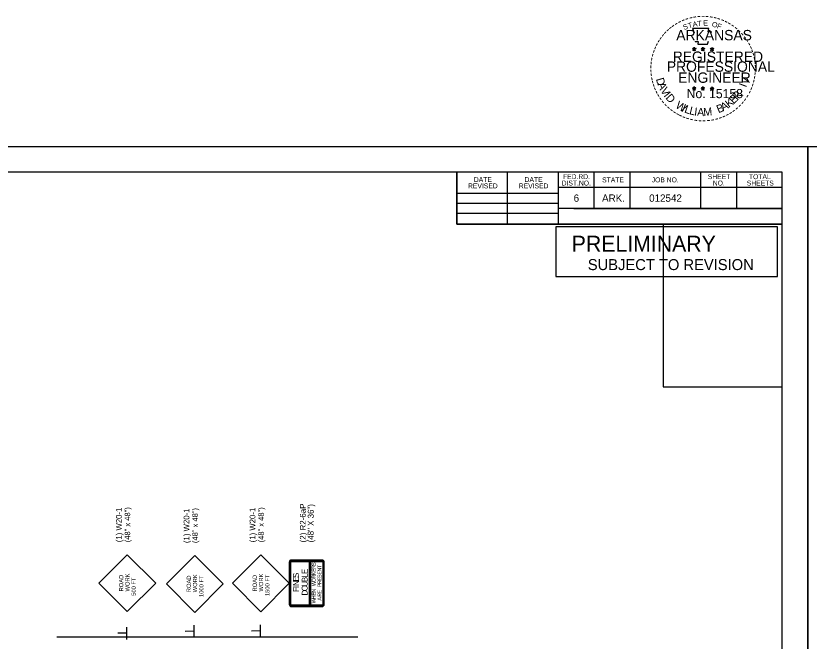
# Model space of a CAD drawing. Extents: x 32485 to 39285, y 55121 to 58033.
# Drawn here: x 35108 to 35886, y 57379 to 57992 of the extents above; entities that cross this region are included whole.
import ezdxf

# ---------------------------------------------------------------- set-up
doc = ezdxf.new("R2010")
doc.units = 0
for name, color, linetype in [('Default', 7, 'Continuous'), ('R_Border', 7, 'Continuous'), ('R_Border Notes', 7, 'Continuous'), ('R_Border PE', 7, 'Continuous'), ('R_Dimension', 7, 'Continuous'), ('R_Draft', 7, 'Continuous'), ('R_Exist Surface', 7, 'Continuous'), ('SHET_Annotations', 7, 'Continuous'), ('SHET_Border-Lines', 7, 'Continuous'), ('SHET_Border-Text', 7, 'Continuous'), ('SHET_Stamp-Seal', 7, 'Continuous')]:
    doc.layers.add(name, color=color, linetype=linetype)

msp = doc.modelspace()

# ---------------------------------------------------------------- linework, layer by layer
at = {"layer": 'Default'}
for p, q in [((35376.16, 57456.07), (35376.16, 57414.67)), ((35376.75, 57456.07), (35376.75, 57414.67)), ((35377.59, 57414.67), (35377.59, 57456.07)), ((35408.28, 57458.21), (35378.3, 57458.21)), ((35408.28, 57457.62), (35378.3, 57457.62)), ((35378.3, 57456.78), (35408.28, 57456.78)), ((35395.97, 57413.96), (35395.97, 57456.78)), ((35395.97, 57456.78), (35396.8, 57456.78)), ((35396.8, 57456.78), (35396.8, 57413.96)), ((35408.99, 57456.07), (35408.99, 57414.67)), ((35409.83, 57414.67), (35409.83, 57456.07)), ((35410.42, 57414.67), (35410.42, 57456.07)), ((35408.28, 57413.96), (35378.3, 57413.96)), ((35378.3, 57413.12), (35408.28, 57413.12)), ((35378.3, 57412.53), (35408.28, 57412.53)), ((35396.8, 57413.96), (35395.97, 57413.96))]:
    msp.add_line(p, q, dxfattribs=at)
for points in [[(34185, 57863.91), (34185, 56763.91), (35885, 56763.91), (35885, 57863.91)], [(35885, 57863.91), (35885, 56763.91), (37585, 56763.91), (37585, 57863.91)], [(35637.83, 57736.64), (35855.24, 57736.64), (35855.24, 57785.18), (35637.83, 57785.18)]]:
    msp.add_lwpolyline(points, close=True, dxfattribs=at)
for centre, radius, start, end in [((35378.3, 57456.07), 2.14, 90, 180), ((35378.3, 57456.07), 1.55, 90, 180), ((35378.3, 57456.07), 0.714, 90, 180), ((35408.28, 57456.07), 2.14, 0.00001, 90.00001), ((35408.28, 57456.07), 1.55, 0, 90.00001), ((35408.28, 57456.07), 0.714, 0, 90.00001), ((35378.3, 57414.67), 2.14, 180, 270), ((35378.3, 57414.67), 1.55, 180, 270.00001), ((35378.3, 57414.67), 0.714, 180, 270.00001), ((35408.28, 57414.67), 2.14, 270, 0.00001), ((35408.28, 57414.67), 1.55, 270.00001, 0), ((35408.28, 57414.67), 0.714, 270.00001, 0)]:
    msp.add_arc(centre, radius, start, end, dxfattribs=at)
at = {"layer": 'R_Border'}
for p, q in [((35217.11, 57463.36), (35189.21, 57435.46)), ((35217.11, 57463.36), (35244.99, 57435.46)), ((35283.48, 57462.55), (35255.58, 57434.66)), ((35283.48, 57462.55), (35311.36, 57434.66)), ((35348.28, 57463.27), (35320.38, 57435.37)), ((35348.28, 57463.27), (35376.16, 57435.37)), ((35189.21, 57435.46), (35217.11, 57407.56)), ((35244.99, 57435.46), (35217.11, 57407.56)), ((35255.58, 57434.66), (35283.48, 57406.76)), ((35311.36, 57434.66), (35283.48, 57406.76)), ((35320.38, 57435.37), (35348.28, 57407.47)), ((35376.16, 57435.37), (35348.28, 57407.47)), ((35216.17, 57392.37), (35216.37, 57380.32)), ((35282.33, 57394.28), (35282.54, 57382.24)), ((35347.42, 57394.58), (35347.63, 57382.54)), ((35216.09, 57386.38), (35207.87, 57386.24)), ((35282.26, 57388.29), (35274.03, 57388.15)), ((35347.35, 57388.59), (35339.12, 57388.45))]:
    msp.add_line(p, q, dxfattribs=at)
at = {"layer": 'R_Border Notes'}
for p, q in [((35540.54, 57787.97), (35540.54, 57838.91)), ((35590.37, 57787.97), (35590.37, 57838.91)), ((35640.19, 57838.91), (35640.19, 57787.97)), ((35675.08, 57838.91), (35675.08, 57803.13)), ((35710.47, 57838.91), (35710.47, 57803.13)), ((35779.73, 57838.91), (35779.73, 57803.13)), ((35815.12, 57838.91), (35815.12, 57803.13)), ((35860, 57823.75), (35640.19, 57823.75)), ((35860, 57823.85), (35860, 57823.85)), ((35540.54, 57818.18), (35640.19, 57818.18)), ((35540.54, 57808.59), (35640.19, 57808.59)), ((35540.54, 57798.59), (35640.19, 57798.59)), ((35860, 57803.13), (35640.19, 57803.13)), ((35655.29, 57803.13), (35860, 57803.13)), ((35860, 57787.97), (35540.54, 57787.97))]:
    msp.add_line(p, q, dxfattribs=at)
for points in [[(34185, 56763.91), (35885, 56763.91), (35885, 57863.91), (34185, 57863.91)], [(35885, 56763.91), (37585, 56763.91), (37585, 57863.91), (35885, 57863.91)], [(34210, 56788.91), (35860, 56788.91), (35860, 57838.91), (34210, 57838.91)], [(35540.54, 57787.97), (35860, 57787.97), (35860, 57838.91), (35540.54, 57838.91)]]:
    msp.add_lwpolyline(points, close=True, dxfattribs=at)
at = {"layer": 'R_Border PE'}
msp.add_lwpolyline([(35773.62, 57961.48), (35774.71, 57958.11), (35771.84, 57960.19), (35775.39, 57960.19), (35772.52, 57958.11), (35773.62, 57961.48)], dxfattribs=at)
at = {"layer": 'R_Dimension'}
for p, q in [((35771.84, 57960.19), (35773.62, 57959.62)), ((35771.84, 57960.19), (35773.13, 57959.96)), ((35771.84, 57960.19), (35773.05, 57959.56)), ((35772.52, 57958.11), (35773.62, 57959.62)), ((35772.52, 57958.11), (35773.16, 57959.35)), ((35772.52, 57958.11), (35773.61, 57959.21)), ((35773.62, 57961.48), (35773.41, 57960.2)), ((35774.71, 57958.11), (35773.61, 57959.2)), ((35773.62, 57959.62), (35773.62, 57961.48)), ((35773.62, 57961.48), (35773.87, 57960.21)), ((35775.39, 57960.19), (35773.62, 57959.62)), ((35774.71, 57958.11), (35773.62, 57959.62)), ((35775.39, 57960.19), (35773.93, 57959.94)), ((35774.71, 57958.11), (35774.01, 57959.59)), ((35775.39, 57960.19), (35774.35, 57959.67)), ((35780.36, 57960.19), (35782.14, 57959.62)), ((35780.36, 57960.19), (35781.65, 57959.96)), ((35780.36, 57960.19), (35781.57, 57959.56)), ((35781.04, 57958.11), (35782.14, 57959.62)), ((35781.04, 57958.11), (35781.68, 57959.35)), ((35781.04, 57958.11), (35782.13, 57959.21)), ((35782.14, 57961.48), (35781.93, 57960.2)), ((35783.22, 57958.11), (35782.13, 57959.2)), ((35782.14, 57959.62), (35782.14, 57961.48)), ((35782.14, 57961.48), (35782.39, 57960.21)), ((35783.91, 57960.19), (35782.14, 57959.62)), ((35783.22, 57958.11), (35782.14, 57959.62)), ((35783.91, 57960.19), (35782.45, 57959.94)), ((35783.22, 57958.11), (35782.52, 57959.59)), ((35783.91, 57960.19), (35782.87, 57959.67)), ((35789.35, 57960.13), (35791.13, 57959.56)), ((35789.35, 57960.13), (35790.64, 57959.9)), ((35789.35, 57960.13), (35790.56, 57959.5)), ((35790.03, 57958.04), (35791.13, 57959.56)), ((35790.03, 57958.04), (35790.67, 57959.29)), ((35790.03, 57958.04), (35791.12, 57959.15)), ((35791.13, 57961.42), (35790.92, 57960.14)), ((35792.22, 57958.04), (35791.12, 57959.14)), ((35791.13, 57959.56), (35791.13, 57961.42)), ((35791.13, 57961.42), (35791.38, 57960.15)), ((35792.9, 57960.13), (35791.13, 57959.56)), ((35792.22, 57958.04), (35791.13, 57959.56)), ((35792.9, 57960.13), (35791.44, 57959.88)), ((35792.22, 57958.04), (35791.52, 57959.53)), ((35792.9, 57960.13), (35791.86, 57959.61)), ((35771.82, 57921.57), (35773.6, 57921)), ((35771.82, 57921.57), (35773.11, 57921.34)), ((35771.82, 57921.57), (35773.03, 57920.94)), ((35772.5, 57919.48), (35773.6, 57921)), ((35772.5, 57919.48), (35773.14, 57920.73)), ((35772.5, 57919.48), (35773.59, 57920.59)), ((35773.6, 57922.86), (35773.39, 57921.58)), ((35774.69, 57919.48), (35773.59, 57920.58)), ((35773.6, 57921), (35773.6, 57922.86)), ((35773.6, 57922.86), (35773.85, 57921.59)), ((35775.37, 57921.57), (35773.6, 57921)), ((35774.69, 57919.48), (35773.6, 57921)), ((35775.37, 57921.57), (35773.91, 57921.32)), ((35774.69, 57919.48), (35773.99, 57920.97)), ((35775.37, 57921.57), (35774.33, 57921.05)), ((35780.33, 57921.57), (35782.11, 57921)), ((35780.33, 57921.57), (35781.62, 57921.34)), ((35780.33, 57921.57), (35781.54, 57920.94)), ((35781.01, 57919.48), (35782.11, 57921)), ((35781.01, 57919.48), (35781.65, 57920.73)), ((35781.01, 57919.48), (35782.1, 57920.59)), ((35782.11, 57922.86), (35781.9, 57921.58)), ((35783.2, 57919.48), (35782.1, 57920.58)), ((35782.11, 57921), (35782.11, 57922.86)), ((35782.11, 57922.86), (35782.36, 57921.59)), ((35783.88, 57921.57), (35782.11, 57921)), ((35783.2, 57919.48), (35782.11, 57921)), ((35783.88, 57921.57), (35782.42, 57921.32)), ((35783.2, 57919.48), (35782.5, 57920.97)), ((35783.88, 57921.57), (35782.84, 57921.05)), ((35789.34, 57921.51), (35791.12, 57920.95)), ((35789.34, 57921.51), (35790.63, 57921.28)), ((35789.34, 57921.51), (35790.55, 57920.89)), ((35790.02, 57919.43), (35791.12, 57920.95)), ((35790.02, 57919.43), (35790.66, 57920.68)), ((35790.02, 57919.43), (35791.11, 57920.54)), ((35791.12, 57922.81), (35790.91, 57921.52)), ((35792.21, 57919.43), (35791.11, 57920.52)), ((35791.12, 57920.95), (35791.12, 57922.81)), ((35791.12, 57922.81), (35791.37, 57921.53)), ((35792.89, 57921.51), (35791.12, 57920.95)), ((35792.21, 57919.43), (35791.12, 57920.95)), ((35792.89, 57921.51), (35791.43, 57921.26)), ((35792.21, 57919.43), (35791.51, 57920.92)), ((35792.89, 57921.51), (35791.85, 57920.99))]:
    msp.add_line(p, q, dxfattribs=at)
for points in [[(35772.05, 57979.96), (35773.42, 57975.75)], [(35789.95, 57975.26), (35790.68, 57976.71), (35787.19, 57976.59), (35787.94, 57979.96), (35772.05, 57979.96)], [(35774.56, 57967.61), (35774.56, 57967.16), (35777.43, 57967.07), (35777.15, 57964.65), (35786.69, 57964.65), (35787.72, 57967.39)], [(35782.14, 57961.48), (35783.22, 57958.11), (35780.36, 57960.19), (35783.91, 57960.19), (35781.04, 57958.11), (35782.14, 57961.48)], [(35791.13, 57961.42), (35792.22, 57958.04), (35789.35, 57960.13), (35792.9, 57960.13), (35790.03, 57958.04), (35791.13, 57961.42)], [(35773.6, 57922.86), (35774.69, 57919.48), (35771.82, 57921.57), (35775.37, 57921.57), (35772.5, 57919.48), (35773.6, 57922.86)], [(35782.11, 57922.86), (35783.2, 57919.48), (35780.33, 57921.57), (35783.88, 57921.57), (35781.01, 57919.48), (35782.11, 57922.86)], [(35791.12, 57922.81), (35792.21, 57919.43), (35789.34, 57921.51), (35792.89, 57921.51), (35790.02, 57919.43), (35791.12, 57922.81)]]:
    msp.add_lwpolyline(points, dxfattribs=at)
for centre, radius in [((35773.61, 57959.62), 0.878), ((35773.61, 57959.62), 0.737), ((35773.61, 57959.62), 0.59), ((35773.61, 57959.62), 0.505), ((35773.61, 57959.62), 0.381), ((35773.61, 57959.62), 0.253), ((35773.61, 57959.62), 0.151), ((35782.13, 57959.62), 0.878), ((35782.13, 57959.62), 0.737), ((35782.13, 57959.62), 0.59), ((35782.13, 57959.62), 0.505), ((35782.13, 57959.62), 0.381), ((35782.13, 57959.62), 0.253), ((35782.13, 57959.62), 0.151), ((35791.13, 57959.56), 0.878), ((35791.13, 57959.56), 0.737), ((35791.13, 57959.56), 0.59), ((35791.13, 57959.56), 0.505), ((35791.13, 57959.56), 0.381), ((35791.13, 57959.56), 0.253), ((35791.13, 57959.56), 0.151), ((35773.59, 57920.99), 0.878), ((35773.59, 57920.99), 0.737), ((35773.59, 57920.99), 0.59), ((35773.59, 57920.99), 0.505), ((35773.59, 57920.99), 0.381), ((35773.59, 57920.99), 0.253), ((35773.59, 57920.99), 0.151), ((35782.11, 57920.99), 0.878), ((35782.11, 57920.99), 0.737), ((35782.11, 57920.99), 0.59), ((35782.11, 57920.99), 0.505), ((35782.11, 57920.99), 0.381), ((35782.11, 57920.99), 0.253), ((35782.11, 57920.99), 0.151), ((35791.12, 57920.94), 0.878), ((35791.12, 57920.94), 0.737), ((35791.12, 57920.94), 0.59), ((35791.12, 57920.94), 0.505), ((35791.12, 57920.94), 0.381), ((35791.12, 57920.94), 0.253), ((35791.12, 57920.94), 0.151)]:
    msp.add_circle(centre, radius, dxfattribs=at)
at = {"layer": 'R_Exist Surface'}
msp.add_line((35148.06, 57382.7), (35443.42, 57382.7), dxfattribs=at)
at = {"layer": 'SHET_Border-Text'}
msp.add_lwpolyline([(35742.99, 57628.25), (35860, 57628.25), (35860, 57787.97), (35742.99, 57787.97)], close=True, dxfattribs=at)
at = {"layer": 'SHET_Stamp-Seal'}
msp.add_lwpolyline([(35750.01, 57787.93), (35750.19, 57787.93), (35750.19, 57787.97), (35750.01, 57787.97)], close=True, dxfattribs=at)

# ---------------------------------------------------------------- texts
at = {"layer": 'Default'}
for s, height, p in [('PRELIMINARY', 15.6, (35653.4, 57760.91)), ('SUBJECT TO REVISION', 10.8, (35669.17, 57742.77))]:
    msp.add_text(s, height=height, dxfattribs=at).set_placement(p)
for s, height, p in [('S', 3.81, (35402.03, 57452.48)), ('R', 3.81, (35402.03, 57449.51)), ('T', 3.81, (35407.74, 57450.07)), ('S', 5.71, (35385.5, 57440.68)), ('E', 5.71, (35394.06, 57444.45)), ('E', 3.81, (35402.03, 57446.51)), ('K', 3.81, (35402.03, 57443.19)), ('N', 3.81, (35407.74, 57446.91)), ('E', 3.81, (35407.74, 57443.9)), ('E', 5.71, (35385.5, 57437.08)), ('N', 5.71, (35385.5, 57432.63)), ('L', 5.71, (35394.06, 57440.74)), ('B', 5.71, (35394.06, 57436.57)), ('O', 3.81, (35402.03, 57436.42)), ('R', 3.81, (35402.03, 57439.96)), ('S', 3.81, (35407.74, 57440.66)), ('E', 3.81, (35407.74, 57437.92)), ('R', 3.81, (35407.74, 57434.68)), ('I', 5.71, (35385.5, 57430.57)), ('F', 5.71, (35385.5, 57426.86)), ('O', 5.71, (35394.06, 57427.6)), ('U', 5.71, (35394.06, 57432.12)), ('W', 3.81, (35402.03, 57432.53)), ('P', 3.81, (35407.74, 57431.53)), ('D', 5.71, (35394.06, 57423.38)), ('N', 3.81, (35402.03, 57426.14)), ('E', 3.81, (35402.03, 57423.13)), ('H', 3.81, (35402.03, 57419.63)), ('E', 3.81, (35407.74, 57425.36)), ('R', 3.81, (35407.74, 57422.12)), ('W', 3.81, (35402.03, 57415.67)), ('A', 3.81, (35407.74, 57418.31))]:
    msp.add_text(s, height=height, rotation=90, dxfattribs=at).set_placement(p)
at = {"layer": 'R_Border'}
for s, height, rotation, p in [('(1) W20-1', 5.71, 90, (35211.71, 57475.64)), ('(48" x 48")', 5.3523, 90, (35219.93, 57475.64)), ('(1) W20-1', 5.71, 90, (35278.08, 57474.83)), ('(48" x 48")', 5.3523, 90, (35286.3, 57474.83)), ('(1) W20-1', 5.71, 90, (35342.88, 57475.55)), ('(48" x 48")', 5.3523, 90, (35351.09, 57475.55)), ('ROAD', 4.11, 90.00045, (35213.13, 57427.4)), ('WORK', 4.11, 90.00004, (35219.3, 57427.32)), (' 500 FT', 4.11, 90.00057, (35225.46, 57421.51)), ('ROAD', 4.11, 90.00045, (35279.51, 57426.6)), ('WORK', 4.11, 90.00004, (35285.67, 57426.52)), ('1000 FT', 4.11, 90.00057, (35291.84, 57421.92)), ('ROAD', 4.11, 90.00045, (35344.3, 57427.31)), ('WORK', 4.11, 90.00004, (35350.47, 57427.23)), ('1500 FT', 4.11, 90.00057, (35356.64, 57422.79))]:
    msp.add_text(s, height=height, rotation=rotation, dxfattribs=at).set_placement(p)
at = {"layer": 'R_Dimension'}
for s, height, rotation, p in [('-', 8.16, 13.63015, (35769.49, 57986.94)), ('-', 8.16, 10.21935, (35772.95, 57987.77)), ('-', 8.16, 5.89682, (35776.66, 57988.33)), ('-', 8.16, 0.18623, (35780.6, 57988.7)), ('-', 8.16, 357.74304, (35784.29, 57988.63)), ('-', 8.16, 352.16172, (35788.08, 57988.34)), ('-', 8.16, 347.20489, (35791.75, 57987.76)), ('-', 8.16, 342.3362, (35794.99, 57986.97)), ('-', 8.16, 36.23174, (35753.21, 57978.82)), ('-', 8.16, 34.06357, (35756.16, 57980.84)), ('-', 8.16, 28.79182, (35759.2, 57982.72)), ('-', 8.16, 24.30721, (35762.43, 57984.34)), ('S', 5.1, 21.59401, (35763.66, 57978.32)), ('-', 8.16, 19.17608, (35765.66, 57985.71)), ('T', 5.1, 16.4036, (35768.32, 57980.01)), ('A', 5.1, 11.21318, (35772.53, 57981.29)), ('T', 5.1, 6.02276, (35776.86, 57982.14)), ('E', 5.1, 0.83234, (35782.5, 57982.7)), ('O', 5.1, 350.4515, (35790.68, 57981.63)), ('F', 5.1, 340.07066, (35795.54, 57980.46)), ('-', 8.16, 337.85509, (35798.74, 57985.83)), ('-', 8.16, 334.12109, (35801.95, 57984.45)), ('-', 8.16, 329.64089, (35804.91, 57983.01)), ('-', 8.16, 325.86266, (35808.19, 57981.17)), ('-', 8.16, 48.42305, (35746.29, 57972.33)), ('-', 8.16, 42.96224, (35748.57, 57974.77)), ('-', 8.16, 38.95066, (35750.78, 57976.89)), ('-', 8.16, 320.52971, (35811.3, 57979)), ('-', 8.16, 315.57859, (35814.35, 57976.51)), ('-', 8.16, 309.87973, (35817.25, 57973.7)), ('-', 8.16, 58.07063, (35740.47, 57964.27)), ('-', 8.16, 54.23247, (35742.13, 57966.96)), ('-', 8.16, 50.61418, (35744.23, 57969.85)), ('-', 8.16, 306.65218, (35819.93, 57970.63)), ('-', 7.14, 303.67529, (35822.41, 57967.73)), ('-', 8.16, 67.77427, (35737.55, 57958.02)), ('-', 8.16, 62.87135, (35738.87, 57961.14)), ('-', 8.16, 299.66835, (35824.04, 57964.64)), ('-', 8.16, 294.66279, (35825.69, 57961.52)), ('-', 8.16, 290.57283, (35827, 57958.58)), ('-', 8.16, 75.46096, (35735.43, 57951.17)), ('-', 8.16, 72.39447, (35736.44, 57954.81)), ('-', 8.16, 285.12326, (35828.19, 57955.62)), ('-', 8.16, 280.54934, (35829.21, 57951.83)), ('-', 8.16, 89.06224, (35734.24, 57940.43)), ('-', 8.16, 85.18634, (35734.37, 57944.01)), ('-', 8.16, 81.20126, (35734.76, 57947.53)), ('-', 8.16, 276.59616, (35830.04, 57947.92)), ('-', 8.16, 274.33011, (35830.35, 57944.23)), ('-', 8.16, 94.19588, (35734.42, 57936.74)), ('-', 8.16, 98.94793, (35734.79, 57933.34)), ('-', 8.16, 263.5172, (35830.42, 57937.61)), ('-', 8.16, 269.94067, (35830.52, 57941.01)), ('-', 8.16, 101.71495, (35735.48, 57929.6)), ('-', 8.16, 105.45785, (35736.3, 57926.56)), ('D', 7.85, 286.28478, (35735.93, 57930.3)), ('V', 7.85, 72.65729, (35825.65, 57924.38)), ('-', 8.16, 255.7626, (35829.5, 57930.82)), ('-', 8.16, 260.99529, (35830.06, 57934.28)), ('-', 8.16, 109.08742, (35737.4, 57923.35)), ('-', 8.16, 114.06432, (35738.69, 57920.31)), ('A', 7.85, 292.78351, (35737.42, 57925.19)), ('V', 7.85, 300.79357, (35740.04, 57919.18)), ('I', 7.85, 69.03009, (35824.51, 57921.63)), ('-', 8.16, 247.88866, (35827.44, 57923.72)), ('-', 8.16, 252.86809, (35828.58, 57927.15)), ('-', 8.16, 115.72885, (35740.25, 57917.15)), ('-', 8.16, 120.44712, (35742.07, 57914.17)), ('I', 7.85, 308.35023, (35743.26, 57913.89)), ('D', 7.85, 311.97742, (35745.05, 57911.51)), ('E', 7.85, 44.01755, (35812.35, 57905.33)), ('R', 7.85, 50.36514, (35816.1, 57908.94)), (',', 7.85, 57.4684, (35819.78, 57913.44)), ('-', 8.16, 239.07125, (35824.09, 57916.67)), ('-', 8.16, 244.61971, (35826.1, 57920.51)), ('-', 8.16, 125.89344, (35744.13, 57911.3)), ('-', 8.16, 130.71812, (35746.48, 57908.49)), ('-', 8.16, 134.22381, (35749.12, 57905.71)), ('W', 7.85, 328.07311, (35754.63, 57902.51)), ('I', 7.85, 336.6877, (35760.68, 57898.89)), ('L', 7.85, 340.3149, (35763.38, 57897.65)), ('B', 7.85, 22.8589, (35797.45, 57896.66)), ('A', 7.85, 28.90423, (35802.02, 57898.57)), ('K', 7.85, 36.91429, (35807.72, 57901.81)), ('-', 8.16, 225.76533, (35817.41, 57907.58)), ('-', 8.16, 231.25377, (35819.85, 57910.46)), ('-', 8.16, 233.84524, (35822.04, 57913.34)), ('-', 8.16, 138.93382, (35751.8, 57903.34)), ('-', 8.16, 144.64634, (35754.63, 57901.27)), ('-', 8.16, 148.08978, (35757.49, 57899.38)), ('-', 8.16, 151.57039, (35760.45, 57897.72)), ('L', 7.85, 346.66249, (35768.28, 57895.89)), ('I', 7.85, 353.01009, (35773.34, 57894.68)), ('A', 7.85, 356.63729, (35776.28, 57894.25)), ('M', 7.85, 4.64735, (35782.83, 57893.95)), ('-', 8.16, 212.24909, (35809.22, 57900.6)), ('-', 8.16, 215.73633, (35811.94, 57902.58)), ('-', 8.16, 221.08509, (35814.74, 57904.99)), ('-', 8.16, 154.60019, (35763.11, 57896.46)), ('-', 8.16, 158.56121, (35766.29, 57895.17)), ('-', 8.16, 162.79826, (35769.79, 57894.08)), ('-', 8.16, 167.55551, (35773.44, 57893.25)), ('-', 8.16, 173.11546, (35777.38, 57892.68)), ('-', 8.16, 176.51827, (35781.19, 57892.41)), ('-', 8.16, 181.59176, (35784.99, 57892.51)), ('-', 8.16, 185.81666, (35789.11, 57892.9)), ('-', 8.16, 191.28576, (35792.87, 57893.57)), ('-', 8.16, 195.47429, (35796.58, 57894.59)), ('-', 8.16, 199.46435, (35799.97, 57895.8)), ('-', 8.16, 204.25161, (35803.19, 57897.21)), ('-', 8.16, 207.35684, (35806.38, 57898.84))]:
    msp.add_text(s, height=height, rotation=rotation, dxfattribs=at).set_placement(p)
for s, height, p in [('ARKANSAS', 10.2, (35756, 57968.3)), ('REGISTERED', 10.2, (35752.54, 57947.14)), ('PROFESSIONAL', 10.1998, (35746.69, 57937.43)), ('ENGINEER', 10.2, (35757.84, 57926.59)), ('No. 15158', 8.961, (35766.21, 57911.54)), ('AAMU', 0.000102, (35781.77, 57893.92))]:
    msp.add_text(s, height=height, dxfattribs=at).set_placement(p)
at = {"layer": 'R_Draft'}
for s, height, p in [('(2) R2-6aP', 5.83, (35392.37, 57475.5)), ('(48" X 36")', 5.8301, (35400.09, 57475.5))]:
    msp.add_text(s, height=height, rotation=90, dxfattribs=at).set_placement(p)
at = {"layer": 'SHET_Annotations'}
for s, p in [('FED.RD.', (35644.81, 57832.05)), ('SHEET', (35786.95, 57832.05)), ('TOTAL', (35827.37, 57832.05)), ('REVISED', (35551.62, 57823.03)), ('DATE', (35557.3, 57829.27)), ('REVISED', (35601.44, 57823.03)), ('DATE', (35607.12, 57829.27)), ('DIST.NO.', (35643.5, 57825.81)), ('STATE', (35683.25, 57828.93)), ('JOB NO.', (35731.92, 57828.93)), ('NO.', (35791.84, 57825.81)), ('SHEETS', (35825.22, 57825.81))]:
    msp.add_text(s, height=4.8, dxfattribs=at).set_placement(p)
at = {"layer": 'SHET_Border-Lines'}
for s, p in [('6', (35655.29, 57809.84)), ('ARK.', (35683.17, 57809.84)), ('012542', (35729.37, 57809.84))]:
    msp.add_text(s, height=7.2, dxfattribs=at).set_placement(p)
at = {"layer": 'SHET_Stamp-Seal'}
for s, height, p in [('PRELIMINARY', 0.013, (35750.02, 57787.95)), ('SUBJECT TO REVISION', 0.009, (35750.03, 57787.93))]:
    msp.add_text(s, height=height, dxfattribs=at).set_placement(p)

doc.saveas('drawing.dxf')
